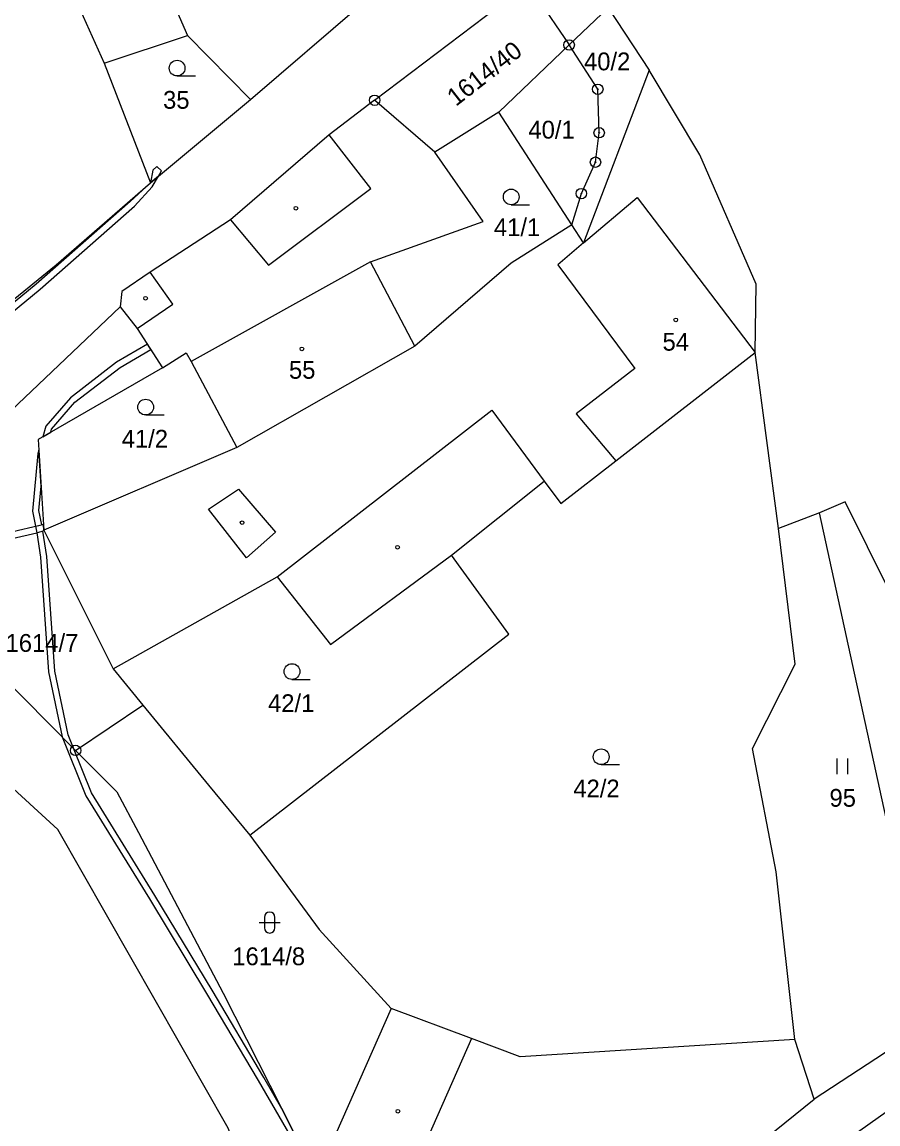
# Model space of a CAD drawing. Extents: x -680203 to -673936, y -1102717 to -1093650.
# Drawn here: x -676626.4 to -676544.7, y -1101089.1 to -1100983.9 of the extents above; entities that cross this region are included whole.
import ezdxf

# ---------------------------------------------------------------- set-up
doc = ezdxf.new("R2010")
doc.units = 0
for name, color, linetype in [('SOxx02xx_Koleje_param další_Popis10', 7, 'Continuous'), ('SOxxxxxx_Koleje_hlavní_body_Popis10', 7, 'Continuous'), ('SOxxxxxx_Koleje_LN_parametry_Popis10', 7, 'Continuous'), ('SOxxxxxx_Koleje_param další_Popis10', 7, 'Continuous'), ('SOxxxxxx_Osa_bod_P', 7, 'Continuous'), ('SOxxxxxx_Staničení_Popis10', 7, 'Continuous'), ('x_prac', 7, 'Continuous')]:
    doc.layers.add(name, color=color, linetype=linetype)

msp = doc.modelspace()

# ---------------------------------------------------------------- linework, layer by layer
at = {"layer": 'SOxx02xx_Koleje_param další_Popis10'}
for centre, radius in [((-676574.15, -1100986.08), 0.5), ((-676574.15, -1100986.08), 0.0303), ((-676571.41, -1100990.31), 0.5), ((-676571.41, -1100990.31), 0.0303), ((-676592.72, -1100991.36), 0.5), ((-676592.72, -1100991.36), 0.0303), ((-676571.28, -1100994.46), 0.5), ((-676571.28, -1100994.46), 0.0303), ((-676571.63, -1100997.27), 0.5), ((-676571.63, -1100997.27), 0.0303), ((-676572.98, -1101000.27), 0.5), ((-676572.98, -1101000.27), 0.0303), ((-676621.27, -1101053.44), 0.5), ((-676621.27, -1101053.44), 0.0303)]:
    msp.add_circle(centre, radius, dxfattribs=at)
at = {"layer": 'SOxxxxxx_Koleje_hlavní_body_Popis10'}
for p, q in [((-676611.58, -1100989.04), (-676609.83, -1100989.04)), ((-676579.68, -1101001.34), (-676577.93, -1101001.34)), ((-676614.58, -1101021.41), (-676612.83, -1101021.41)), ((-676600.61, -1101046.66), (-676598.86, -1101046.66)), ((-676571.09, -1101054.8), (-676569.34, -1101054.8)), ((-676548.54, -1101055.7), (-676548.54, -1101054.2)), ((-676547.54, -1101055.7), (-676547.54, -1101054.2)), ((-676603.24, -1101069.38), (-676603.24, -1101070.38)), ((-676602.24, -1101070.38), (-676602.24, -1101069.38)), ((-676603.74, -1101069.88), (-676601.74, -1101069.88))]:
    msp.add_line(p, q, dxfattribs=at)
for centre in [(-676611.58, -1100988.29), (-676579.68, -1101000.59), (-676614.58, -1101020.66), (-676600.61, -1101045.91), (-676571.09, -1101054.05)]:
    msp.add_circle(centre, 0.75, dxfattribs=at)
for centre, start, end in [((-676602.74, -1101069.38), 0, 180), ((-676602.74, -1101070.38), 180, 359.9879)]:
    msp.add_arc(centre, 0.5, start, end, dxfattribs=at)
at = {"layer": 'SOxxxxxx_Koleje_LN_parametry_Popis10'}
for points in [[(-676614.13, -1100999.24), (-676613.37, -1100998.61), (-676613.07, -1100998.09), (-676613.52, -1100997.69), (-676613.89, -1100998.02)], [(-676616.07, -1101001.04), (-676625.05, -1101008.93), (-676629.81, -1101012.85), (-676636.76, -1101018.44), (-676637.64, -1101018.94), (-676639.33, -1101020.53), (-676638.42, -1101020.07), (-676636.61, -1101019.05), (-676629.43, -1101013.31), (-676624.67, -1101009.39), (-676615.65, -1101001.46), (-676613.97, -1100999.63), (-676613.37, -1100998.61), (-676614.13, -1100999.24)], [(-676624.4, -1101023.49), (-676623.64, -1101023.05), (-676623.56, -1101022.77), (-676621.34, -1101020.2), (-676617.03, -1101016.88), (-676614.1, -1101015.15), (-676614.42, -1101014.64), (-676617.37, -1101016.38), (-676621.76, -1101019.76), (-676624.1, -1101022.47)], [(-676624.79, -1101030.54), (-676624.56, -1101028.2), (-676624.78, -1101024.77), (-676624.87, -1101025.09), (-676625.39, -1101030.58), (-676624.96, -1101032.66), (-676624.28, -1101032.45), (-676624.3, -1101032.41), (-676624.34, -1101031.85), (-676624.5, -1101031.9)]]:
    msp.add_lwpolyline(points, close=True, dxfattribs=at)
for points in [[(-676598.93, -1101092.88), (-676601.57, -1101087.67), (-676603.31, -1101084.67), (-676608.24, -1101076.35), (-676613.7, -1101067.3), (-676619.77, -1101057.49), (-676621.48, -1101053.23), (-676621.98, -1101051.96), (-676623.27, -1101045.86), (-676624.02, -1101034.93), (-676624.39, -1101032.49), (-676624.3, -1101032.41), (-676624.33, -1101031.87), (-676624.8, -1101031.99), (-676629.75, -1101033.13)], [(-676629.73, -1101033.74), (-676624.98, -1101032.65), (-676624.62, -1101034.99), (-676623.87, -1101045.94), (-676622.56, -1101052.14), (-676620.31, -1101057.77), (-676614.22, -1101067.62), (-676608.76, -1101076.65), (-676603.83, -1101084.97), (-676599.53, -1101092.39)]]:
    msp.add_lwpolyline(points, dxfattribs=at)
at = {"layer": 'SOxxxxxx_Koleje_param další_Popis10'}
for centre in [(-676600.24, -1101001.67), (-676614.59, -1101010.26), (-676563.96, -1101012.33), (-676599.67, -1101015.1), (-676605.37, -1101031.69), (-676590.53, -1101034.04), (-676590.5, -1101087.9)]:
    msp.add_circle(centre, 0.175, dxfattribs=at)
at = {"layer": 'SOxxxxxx_Staničení_Popis10'}
for p, q in [((-676619.77, -1100964.08), (-676610.58, -1100985.17)), ((-676593.08, -1100999.79), (-676597.06, -1100994.66)), ((-676602.86, -1101007.1), (-676593.08, -1100999.79)), ((-676572.78, -1101004.98), (-676567.65, -1101000.63)), ((-676567.65, -1101000.63), (-676556.38, -1101015.44)), ((-676606.47, -1101002.78), (-676602.86, -1101007.1)), ((-676572.78, -1101004.98), (-676575.24, -1101007.07)), ((-676593.1, -1101006.8), (-676610.25, -1101016.3)), ((-676575.24, -1101007.07), (-676567.89, -1101016.96)), ((-676612, -1101010.84), (-676614.14, -1101007.77)), ((-676615.38, -1101013.15), (-676612, -1101010.84)), ((-676567.89, -1101016.96), (-676573.48, -1101021.3)), ((-676602.04, -1101036.85), (-676581.53, -1101020.95)), ((-676581.53, -1101020.95), (-676576.52, -1101027.72)), ((-676573.48, -1101021.3), (-676569.68, -1101025.78)), ((-676608.57, -1101030.42), (-676605.73, -1101028.5)), ((-676605.73, -1101028.5), (-676602.2, -1101032.6)), ((-676604.97, -1101035.06), (-676608.57, -1101030.42)), ((-676602.2, -1101032.6), (-676604.97, -1101035.06)), ((-676583.46, -1101080.95), (-676590.62, -1101097.09))]:
    msp.add_line(p, q, dxfattribs=at)
at = {"layer": 'x_prac'}
for p, q in [((-676592.72, -1100991.36), (-676578.1, -1100980.26)), ((-676578.1, -1100980.26), (-676574.15, -1100986.08)), ((-676604.58, -1100991.28), (-676593.98, -1100982.18)), ((-676574.15, -1100986.08), (-676570.43, -1100982.53)), ((-676570.43, -1100982.53), (-676566.51, -1100988.48)), ((-676580.86, -1100992.48), (-676574.15, -1100986.08)), ((-676571.41, -1100990.31), (-676574.15, -1100986.08)), ((-676618.54, -1100987.81), (-676614.13, -1100999.24)), ((-676614.13, -1100999.24), (-676604.58, -1100991.28)), ((-676586.98, -1100996.33), (-676592.72, -1100991.36)), ((-676580.86, -1100992.48), (-676586.98, -1100996.33)), ((-676573.9, -1101003.24), (-676580.86, -1100992.48)), ((-676573.9, -1101003.24), (-676572.98, -1101000.27)), ((-676617.01, -1101011.07), (-676631.13, -1101024.48)), ((-676588.88, -1101014.85), (-676605.89, -1101024.51)), ((-676554.17, -1101032.26), (-676556.38, -1101015.44)), ((-676605.89, -1101024.51), (-676624.3, -1101032.41)), ((-676550.23, -1101030.75), (-676554.17, -1101032.26)), ((-676539.63, -1101079.46), (-676550.23, -1101030.75)), ((-676624.3, -1101032.41), (-676617.7, -1101045.66)), ((-676632.39, -1101042.24), (-676621.27, -1101053.44)), ((-676617.7, -1101045.66), (-676614.86, -1101049.11)), ((-676621.27, -1101053.44), (-676614.86, -1101049.11)), ((-676591.13, -1101078.07), (-676598.26, -1101094.19)), ((-676539.63, -1101079.46), (-676550.75, -1101086.73)), ((-676550.75, -1101086.73), (-676552.59, -1101081.04))]:
    msp.add_line(p, q, dxfattribs=at)
for points in [[(-676631.1, -1100961.64), (-676628, -1100966.79), (-676618.54, -1100987.81)], [(-676618.54, -1100987.81), (-676610.58, -1100985.17), (-676604.58, -1100991.28)], [(-676566.51, -1100988.48), (-676572.78, -1101004.98), (-676573.9, -1101003.24)], [(-676556.38, -1101015.44), (-676556.3, -1101008.92), (-676561.66, -1100996.58), (-676566.51, -1100988.48)], [(-676572.98, -1101000.27), (-676571.63, -1100997.27), (-676571.28, -1100994.46), (-676571.41, -1100990.31)], [(-676592.72, -1100991.36), (-676597.06, -1100994.66), (-676606.47, -1101002.78), (-676614.14, -1101007.77), (-676616.85, -1101009.61), (-676617.01, -1101011.07)], [(-676588.88, -1101014.85), (-676593.1, -1101006.8), (-676582.36, -1101002.92), (-676586.98, -1100996.33)], [(-676653.72, -1101032.27), (-676650.53, -1101030.32), (-676639.91, -1101021.07), (-676636.89, -1101018.24), (-676623.13, -1101007.08), (-676614.13, -1100999.24)], [(-676573.9, -1101003.24), (-676579.68, -1101006.91), (-676588.88, -1101014.85)], [(-676617.01, -1101011.07), (-676615.38, -1101013.15), (-676612.97, -1101016.91)], [(-676612.97, -1101016.91), (-676610.7, -1101015.47), (-676610.25, -1101016.3), (-676605.89, -1101024.51)], [(-676585.39, -1101034.79), (-676576.52, -1101027.72), (-676574.93, -1101029.87), (-676569.68, -1101025.78), (-676556.38, -1101015.44)], [(-676612.97, -1101016.91), (-676624.84, -1101023.74), (-676624.3, -1101032.41)], [(-676526.53, -1101072.56), (-676547.8, -1101029.72), (-676550.23, -1101030.75)], [(-676552.59, -1101081.04), (-676554.38, -1101065.05), (-676556.65, -1101053.25), (-676552.58, -1101045.22), (-676554.17, -1101032.26)], [(-676617.7, -1101045.66), (-676602.04, -1101036.85), (-676596.93, -1101043.34), (-676585.39, -1101034.79)], [(-676604.63, -1101061.54), (-676579.9, -1101042.35), (-676585.39, -1101034.79)], [(-676604.07, -1101096.4), (-676606.71, -1101089.51), (-676622.97, -1101060.99), (-676639.91, -1101045.48), (-676643.49, -1101045.28)], [(-676614.86, -1101049.11), (-676608.57, -1101056.75), (-676604.63, -1101061.54)], [(-676621.27, -1101053.44), (-676617.33, -1101057.4), (-676615.28, -1101061.29), (-676607.19, -1101076.61), (-676598.26, -1101094.19)], [(-676604.63, -1101061.54), (-676598, -1101070.55), (-676591.13, -1101078.07)], [(-676552.59, -1101081.04), (-676578.82, -1101082.69), (-676583.46, -1101080.95), (-676591.13, -1101078.07)], [(-676525.27, -1101079.59), (-676526.22, -1101077.85), (-676538.3, -1101084.04), (-676552.74, -1101094.25)], [(-676575.9, -1101112.46), (-676571.61, -1101104.61), (-676561.78, -1101095.66), (-676550.75, -1101086.73)]]:
    msp.add_lwpolyline(points, dxfattribs=at)

# ---------------------------------------------------------------- texts
at = {"layer": 'SOxxxxxx_Osa_bod_P'}
msp.add_text('1614/40', height=1.7, rotation=38, dxfattribs=at).set_placement((-676584.96, -1100992))
for s, p in [('40/2', (-676572.73, -1100988.5)), ('35', (-676612.92, -1100992.17)), ('40/1', (-676578.04, -1100995.02)), ('41/1', (-676581.33, -1101004.33)), ('54', (-676565.23, -1101015.27)), ('55', (-676600.9, -1101017.95)), ('41/2', (-676616.87, -1101024.53)), ('1614/7', (-676627.96, -1101044.03)), ('42/1', (-676602.9, -1101049.78)), ('42/2', (-676573.75, -1101057.93)), ('95', (-676549.29, -1101058.82)), ('1614/8', (-676606.31, -1101073.95))]:
    msp.add_text(s, height=1.7, dxfattribs=at).set_placement(p)

doc.saveas('drawing.dxf')
